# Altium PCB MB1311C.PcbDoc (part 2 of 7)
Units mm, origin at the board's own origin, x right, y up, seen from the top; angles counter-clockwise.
Board outline 100.03 x 67.03 mm, 6 copper layers (Top Layer, layer2, layer3, layer4, layer5, Bottom Layer), stack 1.208 mm thick; 366 components, 356 nets, 1582 pads, 964 vias.
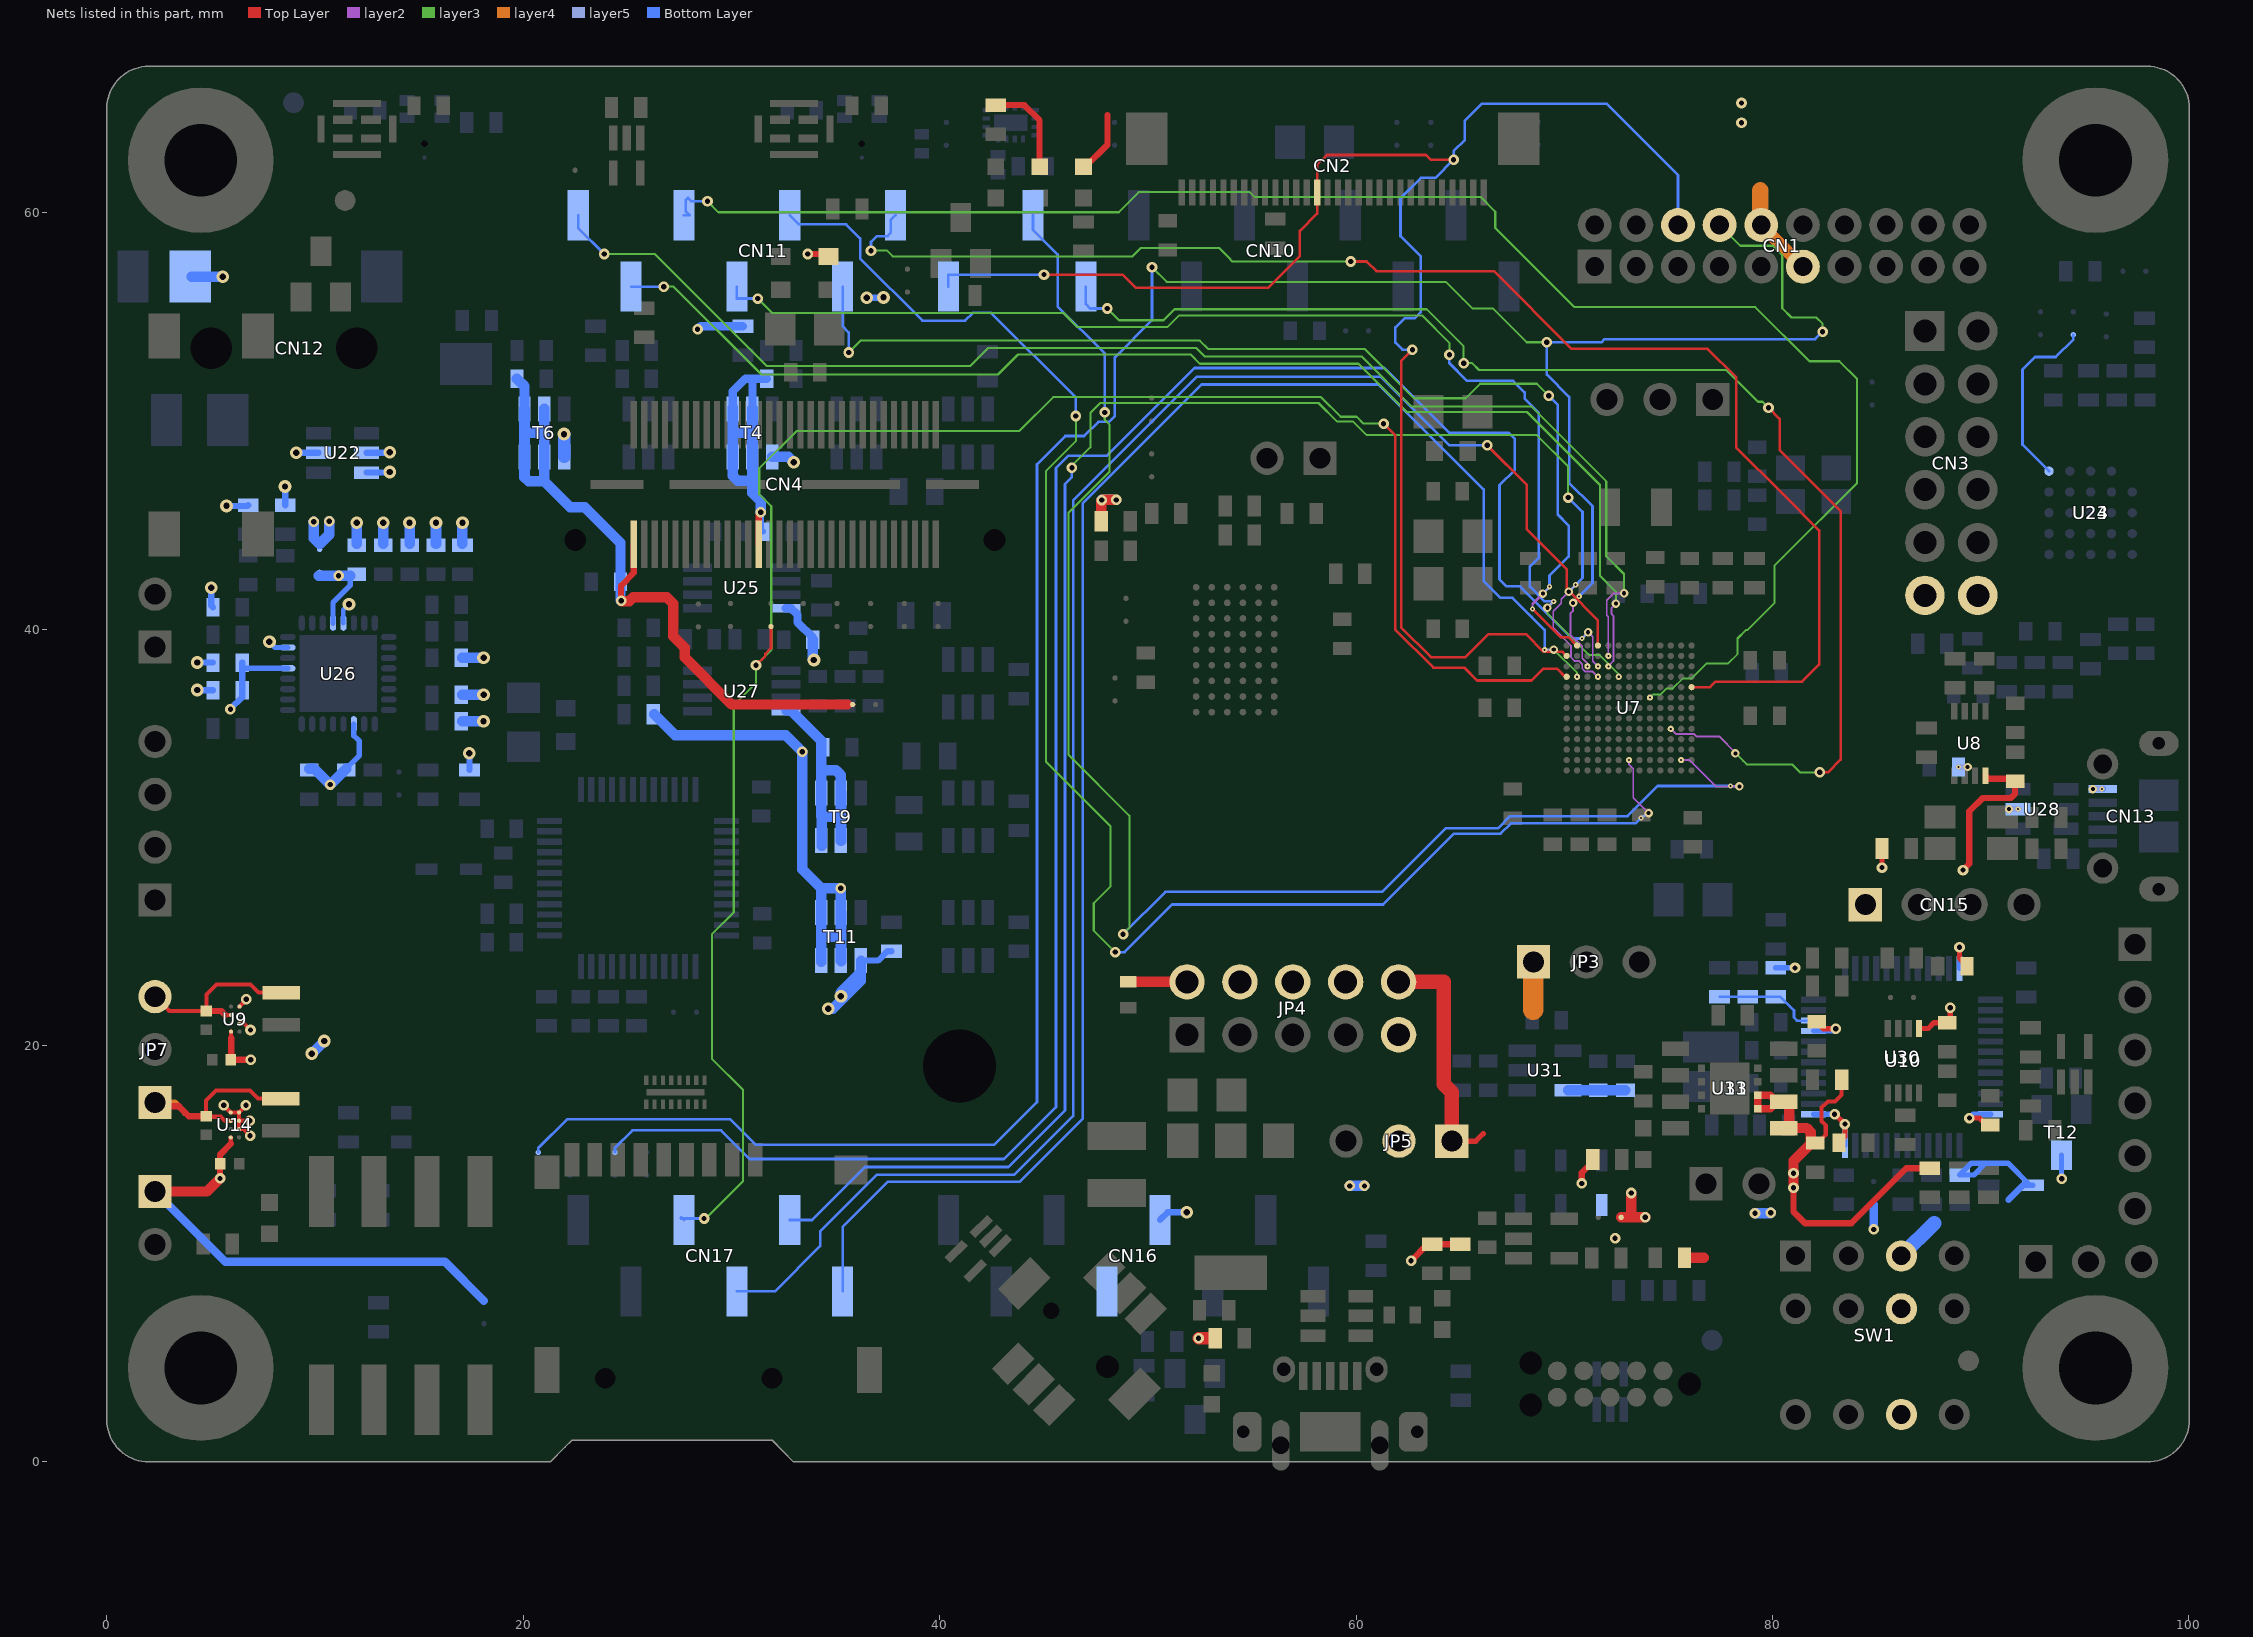
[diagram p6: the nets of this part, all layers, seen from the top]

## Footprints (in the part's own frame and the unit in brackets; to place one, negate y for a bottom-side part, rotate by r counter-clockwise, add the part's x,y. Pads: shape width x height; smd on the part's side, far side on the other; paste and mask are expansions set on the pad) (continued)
ICC_MINI-BGA48_6X8_P075 [mm]
  round 0.32 smd mask+0.05: A1(-1.875,2.625) A2(-1.125,2.625) A3(-0.375,2.625) A4(0.375,2.625) A5(1.125,2.625) A6(1.875,2.625) B1(-1.875,1.875) B2(-1.125,1.875) B3(-0.375,1.875) B4(0.375,1.875) B5(1.125,1.875) B6(1.875,1.875) C1(-1.875,1.125) C2(-1.125,1.125) C3(-0.375,1.125) C4(0.375,1.125) C5(1.125,1.125) C6(1.875,1.125) D1(-1.875,0.375) D2(-1.125,0.375) D3(-0.375,0.375) D4(0.375,0.375) D5(1.125,0.375) D6(1.875,0.375) E1(-1.875,-0.375) E2(-1.125,-0.375) E3(-0.375,-0.375) E4(0.375,-0.375) E5(1.125,-0.375) E6(1.875,-0.375) F1(-1.875,-1.125) F2(-1.125,-1.125) F3(-0.375,-1.125) F4(0.375,-1.125) F5(1.125,-1.125) F6(1.875,-1.125) G1(-1.875,-1.875) G2(-1.125,-1.875) G3(-0.375,-1.875) G4(0.375,-1.875) G5(1.125,-1.875) G6(1.875,-1.875) H1(-1.875,-2.625) H2(-1.125,-2.625) H3(-0.375,-2.625) H4(0.375,-2.625) H5(1.125,-2.625) H6(1.875,-2.625)
  silkscreen extent -3.17,-4.05 3.05,4.18, body extent -3.05,-4.05 3.06,4.06, height 1.2
ICC_MINISO8_3X3_P065 [mm]
  rect 0.4x1.4 smd mask+0.05: 1(0.975,2.125) 2(0.325,2.125) 3(-0.325,2.125) 4(-0.975,2.125) 5(-0.975,-2.125) 6(-0.325,-2.125) 7(0.325,-2.125) 8(0.975,-2.125)
  silkscreen extent -1.6,-1.55 1.6,1.55, body extent -1.6,-2.58 1.6,2.58, height 1.11
ICC_QFN32-EPAD_5X5_P050 [mm]
  oval 0.3x0.75 smd mask+0.05: 1(-1.75,-2.425) 2(-1.25,-2.425) 3(-0.75,-2.425) 4(-0.25,-2.425) 5(0.25,-2.425) 6(0.75,-2.425) 7(1.25,-2.425) 8(1.75,-2.425) 17(1.75,2.425) 18(1.25,2.425) 19(0.75,2.425) 20(0.25,2.425) 21(-0.25,2.425) 22(-0.75,2.425) 23(-1.25,2.425) 24(-1.75,2.425)
  oval 0.75x0.3 smd mask+0.05: 9(2.425,-1.75) 10(2.425,-1.25) 11(2.425,-0.75) 12(2.425,-0.25) 13(2.425,0.25) 14(2.425,0.75) 15(2.425,1.25) 16(2.425,1.75) 25(-2.425,1.75) 26(-2.425,1.25) 27(-2.425,0.75) 28(-2.425,0.25) 29(-2.425,-0.25) 30(-2.425,-0.75) 31(-2.425,-1.25) 32(-2.425,-1.75)
  rect 3.7x3.7 smd mask+0.05: 33(0,0)
  silkscreen extent -2.63,-2.63 2.63,2.63, body extent -2.55,-2.55 2.55,2.55, height 1
ICC_SO8_5X4_P127_DI-DFN8 [mm] "SPT ON MECH-3"
  rect 0.7x1.3 smd paste-10 mask+0.05: 1(-1.905,-2.6) 2(-0.635,-2.6) 3(0.635,-2.6) 4(1.905,-2.6) 5(1.905,2.6) 6(0.635,2.6) 7(-0.635,2.6) 8(-1.905,2.6)
  silkscreen extent -2.58,-2 2.58,2, body extent -2.57,-3 2.57,3, height 1.75
ICC_UFBGA169_7X7_P050 [mm]
  round 0.3 smd mask+0.05: A1(-3,3) A2(-2.5,3) A3(-2,3) A4(-1.5,3) A5(-1,3) A6(-0.5,3) A7(0,3) A8(0.5,3) A9(1,3) A10(1.5,3) A11(2,3) A12(2.5,3) A13(3,3) B1(-3,2.5) B2(-2.5,2.5) B3(-2,2.5) B4(-1.5,2.5) B5(-1,2.5) B6(-0.5,2.5) B7(0,2.5) B8(0.5,2.5) B9(1,2.5) B10(1.5,2.5) B11(2,2.5) B12(2.5,2.5) B13(3,2.5) C1(-3,2) C2(-2.5,2) C3(-2,2) C4(-1.5,2) C5(-1,2) C6(-0.5,2) C7(0,2) C8(0.5,2) C9(1,2) C10(1.5,2) C11(2,2) C12(2.5,2) C13(3,2) D1(-3,1.5) D2(-2.5,1.5) D3(-2,1.5) D4(-1.5,1.5) D5(-1,1.5) D6(-0.5,1.5) D7(0,1.5) D8(0.5,1.5) D9(1,1.5) D10(1.5,1.5) D11(2,1.5) D12(2.5,1.5) D13(3,1.5) E1(-3,1) E2(-2.5,1) E3(-2,1) E4(-1.5,1) E5(-1,1) E6(-0.5,1) E7(0,1) E8(0.5,1) E9(1,1) E10(1.5,1) E11(2,1) E12(2.5,1) E13(3,1) F1(-3,0.5) F2(-2.5,0.5) F3(-2,0.5) F4(-1.5,0.5) F5(-1,0.5) F6(-0.5,0.5) F7(0,0.5) F8(0.5,0.5) F9(1,0.5) F10(1.5,0.5) F11(2,0.5) F12(2.5,0.5) F13(3,0.5) G1(-3,0) G2(-2.5,0) G3(-2,0) G4(-1.5,0) G5(-1,0) G6(-0.5,0) G7(0,0) G8(0.5,0) G9(1,0) G10(1.5,0) G11(2,0) G12(2.5,0) G13(3,0) H1(-3,-0.5) H2(-2.5,-0.5) H3(-2,-0.5) H4(-1.5,-0.5) H5(-1,-0.5) H6(-0.5,-0.5) H7(0,-0.5) H8(0.5,-0.5) H9(1,-0.5) H10(1.5,-0.5) H11(2,-0.5) H12(2.5,-0.5) H13(3,-0.5) J1(-3,-1) J2(-2.5,-1) J3(-2,-1) J4(-1.5,-1) J5(-1,-1) J6(-0.5,-1) J7(0,-1) J8(0.5,-1) J9(1,-1) J10(1.5,-1) J11(2,-1) J12(2.5,-1) J13(3,-1) K1(-3,-1.5) K2(-2.5,-1.5) K3(-2,-1.5) K4(-1.5,-1.5) K5(-1,-1.5) K6(-0.5,-1.5) K7(0,-1.5) K8(0.5,-1.5) K9(1,-1.5) K10(1.5,-1.5) K11(2,-1.5) K12(2.5,-1.5) K13(3,-1.5) L1(-3,-2) L2(-2.5,-2) L3(-2,-2) L4(-1.5,-2) L5(-1,-2) L6(-0.5,-2) L7(0,-2) L8(0.5,-2) L9(1,-2) L10(1.5,-2) L11(2,-2) L12(2.5,-2) L13(3,-2) M1(-3,-2.5) M2(-2.5,-2.5) M3(-2,-2.5) M4(-1.5,-2.5) M5(-1,-2.5) M6(-0.5,-2.5) M7(0,-2.5) M8(0.5,-2.5) M9(1,-2.5) M10(1.5,-2.5) M11(2,-2.5) M12(2.5,-2.5) M13(3,-2.5) N1(-3,-3) N2(-2.5,-3) N3(-2,-3) N4(-1.5,-3) N5(-1,-3) N6(-0.5,-3) N7(0,-3) N8(0.5,-3) N9(1,-3) N10(1.5,-3) N11(2,-3) N12(2.5,-3) N13(3,-3)
  silkscreen extent -3.7,-3.57 3.57,3.7, body extent -3.57,-3.57 3.57,3.57, height 0.61
ICC_UFQFN16-EPAD_2P6X1P8_P040 [mm]
  rect 0.2x0.35 smd mask+0.05: 1(-0.6,-0.775) 2(-0.2,-0.775) 3(0.2,-0.775) 4(0.6,-0.775) 9(0.6,0.775) 10(0.2,0.775) 11(-0.2,0.775) 12(-0.6,0.775)
  rect 0.35x0.2 smd mask+0.05: 5(1.175,-0.6) 6(1.175,-0.2) 7(1.175,0.2) 8(1.175,0.6) 13(-1.175,0.6) 14(-1.175,0.2) 15(-1.175,-0.2) 16(-1.175,-0.6)
  rect 1.6x0.8 smd mask+0.05: 17(0,0)
  silkscreen extent -1.33,-0.92 1.33,0.92, body extent -1.33,-0.92 1.33,0.92, height 0.56
ICC_VFBGA54_6X8_P075 [mm]
  round 0.32 smd mask+0.05: A1(-1.875,3) A2(-1.125,3) A3(-0.375,3) A4(0.375,3) A5(1.125,3) A6(1.875,3) B1(-1.875,2.25) B2(-1.125,2.25) B3(-0.375,2.25) B4(0.375,2.25) B5(1.125,2.25) B6(1.875,2.25) C1(-1.875,1.5) C2(-1.125,1.5) C3(-0.375,1.5) C4(0.375,1.5) C5(1.125,1.5) C6(1.875,1.5) D1(-1.875,0.75) D2(-1.125,0.75) D3(-0.375,0.75) D4(0.375,0.75) D5(1.125,0.75) D6(1.875,0.75) E1(-1.875,0) E2(-1.125,0) E3(-0.375,0) E4(0.375,0) E5(1.125,0) E6(1.875,0) F1(-1.875,-0.75) F2(-1.125,-0.75) F3(-0.375,-0.75) F4(0.375,-0.75) F5(1.125,-0.75) F6(1.875,-0.75) G1(-1.875,-1.5) G2(-1.125,-1.5) G3(-0.375,-1.5) G4(0.375,-1.5) G5(1.125,-1.5) G6(1.875,-1.5) H1(-1.875,-2.25) H2(-1.125,-2.25) H3(-0.375,-2.25) H4(0.375,-2.25) H5(1.125,-2.25) H6(1.875,-2.25) J1(-1.875,-3) J2(-1.125,-3) J3(-0.375,-3) J4(0.375,-3) J5(1.125,-3) J6(1.875,-3)
  silkscreen extent -3.17,-4.05 3.05,4.18, body extent -3.05,-4.05 3.05,4.05, height 1.01
ICC_VSSOP8_DCU_R-PDSO-G8_2X2P30_P050 [mm]
  rect 0.3x0.8 smd mask+0.05: 1(-0.75,-1.55) 2(-0.25,-1.55) 3(0.25,-1.55) 4(0.75,-1.55) 5(0.75,1.55) 6(0.25,1.55) 7(-0.25,1.55) 8(-0.75,1.55)
  silkscreen extent -1.05,-1.2 1.05,1.2, body extent -1.05,-1.62 1.05,1.62, height 0.9
IND_MURATA_DFE201610C [mm]
  rect 0.65x1.8 smd mask+0.05: 1(-0.775,0) 2(0.775,0)
  silkscreen extent -0.33,-0.9 0.33,0.9, body extent -1.1,-0.9 1.1,0.9, height 1
L0603 [mm]
  rect 0.8x0.95 smd mask+0.05: 1(-0.8,0) 2(0.8,0)
  silkscreen extent -1.33,-0.6 1.33,0.6, body extent -0.87,-0.47 0.87,0.47, height 0.95
LED_0603_GREEN_H0P8 [mm]
  rect 0.8x0.8 smd mask+0.05: 1(-0.75,0) 2(0.75,0)
  silkscreen extent -0.25,-0.4 1.25,0.4, body extent -0.8,-0.4 0.8,0.4, height 0.8
LED_0603_ORANGE_H0P4 [mm]
  rect 0.8x0.8 smd mask+0.05: 1(-0.75,0) 2(0.75,0)
  silkscreen extent -0.25,-0.4 1.25,0.4, body extent -0.8,-0.4 0.79,0.4, height 0.4
LED_0603_RED_H0P4 [mm]
  rect 0.8x0.8 smd mask+0.05: 1(-0.75,0) 2(0.75,0)
  silkscreen extent -0.25,-0.4 1.25,0.4, body extent -0.8,-0.4 0.79,0.4, height 0.4
LED_BI-GR_HSMF-A201-A00J1 [mm]
  rect 1.1x1.5 smd mask+0.05: 1(-0.75,-1.5) 2(-0.75,1.5) 3(0.75,1.5) 4(0.75,-1.5)
  silkscreen extent -1.65,-1.85 1.65,1.85, body extent -1.5,-1.85 1.5,1.85, height 2.1
MIC_HCLGA_3X4X1_4LD [mm]
  rect 0.4x0.95 smd paste+0 mask+0.05: 1(0.45,-0.675) 2(0.45,0.675) 3(-0.45,0.675) 4(-0.45,-0.675)
  rect 1.3x0.35 smd paste+0 mask+0.05: 5(0,-1.725) 6(0,1.725)
  rect 0.35x2.3 smd paste+0 mask+0.05: 7(1.225,0) 8(-1.225,0)
  silkscreen extent -1.55,-2.05 1.55,2.05, body extent -1.45,-1.95 1.45,1.95, height 1
MIC_STM_MP23DB01MMTR#1 [mm]
  rect 0.725x0.522 smd mask+0.05: 1(-0.838,1.364) 2(-0.838,0.542) 4(0.838,0.542) 5(0.838,1.364)
  round 0.2 smd mask+0.05: 3(0,-1.373)
  round 0 hole 0.325 unplated mask+0.05: 6(0,-0.71)
  Top Layer drawing of 16384 lines, arcs and shapes, not listed
  silkscreen extent -1.33,-1.75 1.33,1.75, body extent -1.33,-1.76 1.33,1.75, height 1.09
MIC_STM_MP23DB01MMTR#2 [mm]
  rect 0.725x0.522 smd mask+0.05: 1(-0.838,1.364) 2(-0.838,0.542) 4(0.838,0.542) 5(0.838,1.364)
  round 0.2 smd mask+0.05: 3(0,-1.373)
  round 0 hole 0.325 unplated mask+0.05: 6(0,-0.71)
  Top Layer circle w0.3: c0,-0.71 r0.663
  silkscreen extent -1.33,-1.75 1.33,1.75, body extent -1.33,-1.76 1.33,1.75, height 1.09
MOS_SOT23 [mm]
  rect 1x1.4 smd mask+0.05: 1(-0.95,-1.1) 2(0.95,-1.1) 3(0,1.1)
  silkscreen extent -1.63,-0.82 1.63,0.82, body extent -1.56,-1.25 1.56,1.25, height 1.1
MOS_SOT23-5L [mm]
  rect 0.6x1.3 smd mask+0.05: 1(-0.95,-1.1) 2(0,-1.1) 3(0.95,-1.1) 4(0.95,1.1) 5(-0.95,1.1)
  silkscreen extent -1.6,-0.95 1.6,0.97, body extent -1.52,-1.25 1.52,1.25, height 1.45
MOS_SOT23-6L [mm]
  rect 0.6x1.2 smd mask+0.05: 1(-0.95,-1.15) 2(0,-1.15) 3(0.95,-1.15) 4(0.95,1.15) 5(0,1.15) 6(-0.95,1.15)
  silkscreen extent -1.53,-0.87 1.53,0.87, body extent -1.52,-1.5 1.52,1.5, height 1.3
NPN_SOT23 [mm]
  rect 1x1.4 smd mask+0.05: 1(-0.95,-1.1) 2(0.95,-1.1) 3(0,1.1)
  silkscreen extent -1.63,-0.82 1.63,0.82, body extent -1.56,-1.25 1.56,1.25, height 1.1
PTH_350_700 [mm]
  round 7 hole 3.5 mask+0.05: 1(0,0)
  silkscreen extent -3.75,-3.75 3.75,3.75
R0402 [mm]
  rect 0.51x0.7 smd mask+0.05: 1(-0.45,0) 2(0.45,0)
  silkscreen extent -0.72,-0.43 0.72,0.43, body extent -0.52,-0.3 0.52,0.3, height 0.4
R0603 [mm]
  rect 0.64x1 smd mask+0.05: 1(-0.7,0) 2(0.7,0)
  silkscreen extent -1.05,-0.58 1.05,0.58, body extent -0.9,-0.5 0.9,0.5, height 0.56
R0805 [mm]
  rect 0.85x1.3 smd mask+0.05: 1(-0.875,0) 2(0.875,0)
  silkscreen extent -0.33,-0.67 0.33,0.67, body extent -1.05,-0.68 1.05,0.68, height 0.65
REG_SOT223-TAB [mm]
  rect 1.5x1.65 smd mask+0.05: 1(-2.3,-3.175) 2(0,-3.175) 3(2.3,-3.175)
  rect 3.5x1.65 smd mask+0.05: 4(0,3.175)
  silkscreen extent -3.35,-2.15 3.35,2.12, body extent -3.35,-3.48 3.35,3.48, height 1.8
SOLDER-BRIDGE_R0603-0R [mil]
  round 10 smd paste-393.7: 1(-19.69,0) 2(23.62,0)
  Top Layer region: -5.91,19.68 13.78,0 -5.91,-19.68 47.24,-19.68 47.24,19.68 -5.91,19.68
  Top Layer region: -47.24,-19.68 -47.24,19.68 -15.75,19.68 3.94,0 -15.75,-19.68 -47.24,-19.68
  silkscreen extent -50,-23 50,23, body extent -36,-20 36,20, height 22
SWI_GRAYHILL-INC_EDG-501S_DI [mm] "ATTENTION DOUBLE IMPLANTATION AVEC SWITCH RA PROJET MB1311_RevA"
  rect 1.5x1.5 hole 0.9 mask+0.05: 1(-3.81,-3.81)
  round 1.5 hole 0.9 mask+0.05: 2(-1.27,-3.81) 3(1.27,-3.81) 4(3.81,-3.81) 5(3.81,-1.27) 5(3.81,3.81) 6(1.27,-1.27) 6(1.27,3.81) 7(-1.27,-1.27) 7(-1.27,3.81) 8(-3.81,-1.27) 8(-3.81,3.81)
  Top Layer region: 3.15,-1.32 4.47,-1.32 4.47,3.86 3.15,3.86 3.15,-1.32
  Top Layer region: -4.47,-1.32 -3.15,-1.32 -3.15,3.86 -4.47,3.86 -4.47,-1.32
  Top Layer region: -1.93,-1.32 -0.61,-1.32 -0.61,3.86 -1.93,3.86 -1.93,-1.32
  Top Layer region: 0.61,-1.32 1.93,-1.32 1.93,3.86 0.61,3.86 0.61,-1.32
  silkscreen extent -5.85,-5 5.85,5, body extent -5.85,-5 5.85,5, height 6.9
SWI_WEALTHMETAL_TD-0341_4P [mm]
  rect 1.52x2.16 smd mask+0.05: 1(-2.25,-4.75) 2(-2.25,4.75) 3(2.25,-4.75) 4(2.25,4.75)
  silkscreen extent -3,-3.5 3,3.5, body extent -3,-5.15 3,5.15, height 7.55
SWI_XIEJIA_MT-008A_6P [mm]
  rect 1.8x1.1 smd mask+0.05: 1(-3.1,1.4) 2(-3.1,0) 3(-3.1,-1.4) 4(3.1,1.4) 5(3.1,0) 6(3.1,-1.4)
  rect 2.2x1.4 smd mask+0.05: 7(0,3.75) 8(0,-3.75)
  round 0 hole 0.8 unplated mask+0.05: NPTH1(0,1.9)
  round 0 hole 1.1 unplated mask+0.05: NPTH2(0,-1.9)
  silkscreen extent -3.7,-3.7 3.7,3.7, body extent -3.85,-3.75 3.85,3.75, height 5.2

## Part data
B1: library part "SW PUSHBUTTON", "SE Push Button TD-0341 [RESET/Black]"
B2: library part MT-008A, "Joystick"
C1 C2 C3 C5 C7 C10 C12 C14 C15 C16 C17 C18 C19 C20 C21 C22 C23 C24 C26 C27 C28 C29 C31 C32 C34 C35 C37 C40 C44 C45 C48 C49 C52 C53 C57 C60 C61 C64 C65 C66 C69 C70 C72 C73 C74 C78 C79 C80 C81 C83 C84 C85 C88 C89 C90 C92 C94 C97: library part Cap, "Capacitor,100nF,10%,16V,X7R,0603,YAGEO"
C4 C36 C46: library part "Cap Pol1", "TAN Capacitor,10uF,10%,16V,A Type,AVX"
C6: library part "Cap Pol1", "TAN Capacitor,4.7uF,10%,16V,A Type,AVX"
C8 C13 C75 C87: library part "Cap Pol1", "Tan Capacitor,1uF,10%,16V,Tan-A,TAJA105K016R"
C9 C11: library part Cap, "Capacitor,5.6pF,0.25P,50V,NPO,0603"
C25: library part Cap_2.2uF_X5R_10%_0603, "Capacitor,2.2uF,16V,X5R,10%,0603,YAGEO"
C30 C38: library part Cap, "Capacitor,10uF,0402,GRM155R60J106ME11"
C33 C42: library part Cap, "Capacitor,0402,4.7uF"
C39: library part "Cap Pol1", "Tan Capacitor,10uF,10%,25V,Tan-B,TAJB106K025RNJ"
C41 C55 C56 C62 C63 C67 C68 C71 C82 C95 C96: library part Cap, "Capacitor,1uF,0603,16V,10%,X5R,YAGEO"
C43: library part Cap, "Capacitor,4.7uF,16V, X5R,10%,0603"
C47: library part Cap_1uF_X5R_10%_0603, "Capacitor,1uF,16V,X5R,10%,0603,YAGEO"
C50 C51: library part Cap, "Capacitor,6.8pF,0.25P,50V,NPO,0603"
C54: library part Cap, "Capacitor,10uF,10%,10V,X5R,0603,C1608X5R1A106KT000E"
C58 C59: library part Cap, "Capacitor,22nF,10%,25V,X7R,0603"
C76 C77: library part Cap, "Capacitor,150pF,0603,50V,5%,NPO"
C86 C91: library part Cap, "Capacitor,10nF,0603,50V,10%,X7R,YAGEO;"
C93 C98: library part Cap, "Capacitor,10pF,5%,50V,NPO,0603,YAGEO"
C99 C100 C101: library part Cap, "Capacitor,100nF,10%,16V,X7R,0603,YAGEO", Manuf_1=YAGEO, Manuf_Part_1=CC0603KRX7R7BB104
CN1: library part "Header 10X2A", "Header, 10-Pin, Dual row"
CN2: library part FPU330ZH-BT1D3-CA, "TOWNES -  Connector FFC/FPC ZIF 0.5mm 30 pins, Lower Contacts"
CN3: library part "Header 6X2A", "Header, 6-Pin, Dual row"
CN4: library part QSH-030-01-F-D-A, "HIGH SPEED SOCKET STRIP, .5mm PITCH, 60 PINS"
CN5: library part "Header 6", "Header, 6-Pin"
CN6: library part MR01A-01211, "micro-SD card connector top mount push-push", Manuf_1=ATOM
CN7: library part SSM-104-L-DH, "Header, 5-Pin, Dual row"
CN8: library part Tag-10_C, "Footprint for TC2050-IDC-430 plug of nails (TM) cable for MP430"
CN9: library part 475900001
CN10: library part "Header 10X1_Female", "Header, 10-Pin, Single row,female"
CN11 CN16: library part "Header 8X1_Female", "Header, 8-Pin, Single row,female"
CN12: library part PJ3028B-3
CN13: library part 1050170001
CN14 CN15: library part "Header 4", "Header, 4-Pin"
CN17: library part "Header 6X1_Female", "Header, 6-Pin, Single row,female"
D1 D2: library part ESDA7P60-1U1M, "High power transient voltage suppressor, 7V breakdown"
D3 D4 D5 D6 D7: library part BAT60JFILM, "BAT60JFILM"
H1 H2 H3 H4: library part "POSITION HOLE"
JP1: library part Jumper3, "Jumper 3 pins"
JP2 JP8 JP9: library part JP2
JP3 JP5 JP7 JP10: library part Jumper3
JP4: library part "Header 5X2M", "Pin Header male,2.54mm,2*5,L=11.6,180,1U,DIP"
JP6: library part JP2, "2 PIN Jumper"
L1 L2 L3: library part Inductor, "100uH Bead"
L4 L5: library part Inductor, "Inductor"
L6: library part BEAD_600R_350MA_0603, "Bead,600R,350mA,0603,FCM1608KF-601T03,Tai-tech"
LD1: library part LED2, "LED,Orange,0603"
LD2 LD3 LD6 LD8: library part LED2, "LED,Green,0603"
LD4: library part LD_BICOLOR_CMS, "Bicolor Led"
LD5 LD7: library part LED2, "LED, Red ,0603"
R1 R7 R8 R9 R10 R29 R34 R44 R47 R48 R80 R83 R96 R101: library part res1, "Resistor,10K,0603,1%,YAGEO"
R2: library part res1, "Resistor, 510R , 0603,1%,YAGEO"
R3: library part res1, "Resistor,680R,0603,1%,YAGEO"
R4: library part res1, "Resistor, 22 ,0603,1%,YAGEO"
R5 R95: library part res1, "Resistor,510R,0603,1%,YAGEO"
R6: library part res1, "Resistor, 1M , 0603"
R11 R13 R14 R17 R20 R22 R24 R31 R41 R61 R79 R82 R88 R97: library part res1, "Resistor, 0 ,0603,1%,YAGEO"
R12: library part res1, "Resistor,10K,0603,1%,YAGEO", Manuf_1=YAGEO, Manuf_Part_1=RC0603FR-07100KL
R15 R16 R18 R19 R25 R49 R50 R59 R74 R84 R86 R87 R89 R90 R91 R102 R106: library part res1, "Resistor,100K,0603,1%,YAGEO"
R21 R23 R26 R28 R30 R32 R35 R42 R75 R94 R110 R111 R115: library part res1, "Resistor, 100 ,0603,1%,YAGEO"
R27 R64: library part res1, "Resistor,2.2K,0603,1%,YAGEO"
R33 R37: library part res1, "Resistor"
R36: library part res1, "Resistor,36K,0603,1%,YAGEO"
R38: library part res1, "Resistor, 620R , 0603,1%,YAGEO"
R39 R40 R113: library part res1, "Resistor, 47K,0603,1%,YAGEO"
R43: library part res1, "Resistor, 330R , 0603,1%,YAGEO"
R45 R46: library part Res_10K_1%_0402, "Resistor,10K,0402,1%,YAGEO"
R51 R52 R53 R63 R67 R68 R69 R71 R72 R73 R78: library part res1, "Resistor, 33 ,0603,1%,YAGEO"
R54 R56 R107 R108 R112: library part Res1, "Resistor"
R55: library part Res_1_1%_0805, "Resistor,1,0805,1%,YAGEO"
R57 R58: library part res1, "Resistor,50R,0603,1%,YAGEO"
R60 R65: library part res1, "Resistor,6.04K,0603,1%,YAGEO"
R62: library part Res_10K_1%_0805, "Resistor,10K,0805,1%,YAGEO"
R66 R76: library part res1, "Resistor,300K,0603,1%,YAGEO"
R70: library part res1, "Resistor,11K,0603,1%,YAGEO"
R77: library part res1, "Resistor,357K,0603,1%,YAGEO"
R81: library part Res_24_1%_0805, "Resistor,24,0805,1%,YAGEO"
R85: library part Res_620_1%_0805, "Resistor,620,0805,1%,YAGEO"
R92 R93 R105: library part res1, "Resistor,4.7K,0603,1%,YAGEO"
R98 R99 R100: library part res1, "Resistor,1.5K,0603,1%,YAGEO"
R103: library part Res_0_5%_0402, "Resistor,0,0603,5%,YAGEO"
R104: library part res1, "Resistor,2.7K,0603,1%,YAGEO"
R109: library part res1, "Resistor,1K,0603,1%"
R114: library part res1, "Resistor, 10K,0603,1%,YAGEO"
R116: library part res1, "Resistor,56K,0603,1%,YAGEO", Manuf_1=YAGEO, Manuf_Part_1=RC0603FR-0756KL
R117: library part res1, "Resistor,6.8K,0603,1%,YAGEO", Manuf_1=YAGEO, Manuf_Part_1=RC0603FR-076K8L
R118 R119 R120: library part res1, "Resistor, 0 ,0603,1%,YAGEO", Manuf_1=YAGEO, Manuf_Part_1=RC0603JR-070RL
SB1 SB2 SB3 SB5 SB6 SB8 SB9 SB10 SB11 SB12 SB14 SB15 SB22 SB23 SB24 SB26 SB29 SB30 SB31 SB33 SB35 SB37: library part SB_ON, "Solder Bridge ON"
SB4 SB7 SB13 SB16 SB17 SB18 SB19 SB20 SB21 SB25 SB27 SB28 SB32 SB34 SB36 SB39: library part SB_OFF, "Solder Bridge OFF"
SB38: library part SB_ON, "Solder Bridge ON", Manuf_1=YAGEO, Manuf_Part_1=RC0603JR-070RL
SW1: library part EDG-501S, "Gold Plated Contacts,4PST,1x4 Switch"
T1: library part 2N7000
T2 T3 T4 T5 T6 T7 T8 T9 T10 T11: library part STT7P2UH7, "STripFET VII DeepGATE Power MOSFET, P-CHANNEL 20 V, 0.0146, 7 A - SOT23-6L"
T12 T13: library part NPN, "NPN Bipolar Transistor"
U1 U2: library part MP34DT01TR, "MEMS audio sensor"
U3 U12 U17: library part ESDALC6V1W5, "Quad Transil array for ESD protection"
U4: library part ESDA6V1L, "Dual Transil array ESD protection"
U5: library part IS66WV1M16EBLL-55BLI, "16M bit static RAMs organized as 1024K words by 16 bits"
U6: library part IS66WVC2M16ECLL-7010BLI, "32Mb Burst PSRAM , 104 MHz, 3V, organized as 2M words by 16 bits"
U7: library part STM32L4R9AII6U
U8 U10: library part SN74LVC2T45DCUT
U9 U14: library part TPS62743, "High Efficiency Buck Converter"
U11: library part ST890CDR
U13: library part EMIF06-MSD02N16, "6-line IPAD, EMI filter and ESD for SDcard2.0"
U15: library part LD1117S18TR, "Adjustable and fixed low drop positive voltage regulator"
U16: library part STMPS2141STR, "Enhanced single channel power switches"
U18: library part USBLC6-4SC6, "USB ESD protection"
U19 U20: library part MP23DB01MM, "MEMS micro"
U21: library part STG3692QTR, "Low voltage high bandwidth quad SPDT switch"
U22: library part ESDA6V1BC6, "Quad Bidir supressor ESD protection"
U23: library part MT35XL512ABA1G12-0SIT, "512Mb, 3V, Octal I/O XTRM Flash Memory, 133 MHz, DDR"
U24: library part MX25LM51245GXDI00, "512Mb, 3V, CMOS, MXSMIO Octal I/O FLASH MEMORY, 133 MHz, DTR"
U25 U27: library part TSZ122IST, "Very high accuracy (5 ?) zero drift 5 V dual OpAmp"
U26: library part CS42L51-CNZ, "Low-Power, Stereo Codec with Headphone Amp"
U28: library part USBLC6-2SC6
U29: library part MFX, "Multifunction expander"
U30: library part STM32F10x(48pin), "IC,STM32F103CBT6,LQFP-48"
U31: library part LD3985M33R, "Ultra low drop-low noise BiCMOS voltage, regulators low ESR capacitors compatible"
U32: library part ESDALC6V1W5, "Quad Transil array for ESD protection", Manuf_1=STM
U33: library part ST890DTR, Manuf_1=ST
X1: library part CRYSTAL_32K, "32.768kHz Crystal"
X2: library part NX3225GA-16MHz-EXS00A-CG04815
X3: library part XTAL_8M_NX3225GD, "Crystal 8Mhz, 8pF, -+50PPM, SMD"

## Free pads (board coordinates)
  round 1 smd far side mask+0.5: 2(8.971,65.279) 2(77.095,5.839)
  round 1 smd mask+0.5: 2(11.446,60.584) 2(89.418,4.852)
  round 0.1 hole 3.5 unplated: 3(40.963,19.013)

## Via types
v1: diameter 0.508, hole 0.254, Top Layer to Bottom Layer, tented both sides, 462 vias
v2: diameter 0.61, hole 0.305, Top Layer to Bottom Layer, tented both sides, 126 vias
v3: diameter 0.406, hole 0.203, layer2 to layer5, tented both sides, 109 vias
v4: diameter 0.25, hole 0.1, Top Layer to layer2, tented both sides, 80 vias
v5: diameter 0.25, hole 0.1, Top Layer to layer3, tented both sides, 78 vias
v6: diameter 0.25, hole 0.1, layer5 to Bottom Layer, tented both sides, 52 vias
v7: diameter 0.406, hole 0.203, Top Layer to Bottom Layer, tented both sides, 48 vias
v8: diameter 0.508, hole 0.254, layer2 to layer5, tented both sides, 4 vias
v9: diameter 0.406, hole 0.203, layer2 to layer5, 3 vias
v10: diameter 0.25, hole 0.1, layer5 to Bottom Layer, tented bottom, 1 vias
v11: diameter 0.25, hole 0.1, Top Layer to layer3, tented top, 1 vias

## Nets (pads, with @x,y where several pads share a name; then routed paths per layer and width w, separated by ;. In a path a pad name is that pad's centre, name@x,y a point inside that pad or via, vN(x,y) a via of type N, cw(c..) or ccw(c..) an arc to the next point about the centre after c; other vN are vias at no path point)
1V8_CODEC: C57.1 C71.1 C74.1 C81.1 C82.1 SB29.2 U26.5 U26.12 U26.27 | length 13.6
  Bottom Layer w0.254: C71.1@6.672,38.113 U26.5@8.693,38.113 ; U26.12@10.863,40.283 10.863,41.269 11.688,42.093 C57.1@11.688,42.562 ; C81.1@11.494,33.291 12.129,33.926 12.129,34.615 11.863,34.881 U26.27@11.863,35.443
  Bottom Layer w0.3: v1(5.94,36.152) 5.94,36.162 6.505,36.727 C74.1@6.505,37.057 C71.1@6.505,38.387
  Bottom Layer w0.508: C82.1@9.716,33.291 9.97,33.291 v1(10.732,32.529) C81.1@11.494,33.291 ; 10.181,42.562 C57.1@11.688,42.562
  other v1: 11.134,42.559
1V8_LCD: C60.1 C99.2 CN4.60 SB39.2 T6.1 T6.2 T6.5 T6.6 | length 35.3
  Top Layer w0.3: v1@24.675,41.375 24.703,41.375 24.703,42.089 25.313,42.699 CN4.60@25.313,44.073
  Top Layer w0.5: v1@24.725,41.325 25.1,41.325 25.294,41.519 26.906,41.519 27.2,41.225 27.2,39.662 27.76,39.101 27.76,38.64 30.025,36.375 35.575,36.375
  Bottom Layer w0.5: C99.2@19.7,52.025 20.063,51.662 T6.1@20.063,50.573 ; 20.063,47.292 20.26,47.095 21.013,47.095 22.25,45.858 22.96,45.858 24.673,44.145 C60.1@24.673,42.273 24.673,41.383 v1(24.703,41.353)
  Bottom Layer w0.508: 20.063,47.292 20.063,49.44 ; T6.1@20.063,50.573 20.063,49.44 ; 21.013,47.095 T6.5@21.013,48.273 21.013,49.423 ; T6.2@21.013,50.573 21.013,49.423 ; 20.063,49.44 20.08,49.423 21.013,49.423
3V3_LCD: C52.2 C101.2 CN4.36 T4.1 T4.2 T4.5 T4.6 | length 17.3
  Top Layer w0.3: CN4.36@31.313,44.073 31.313,45.503 v1(31.413,45.603)
  Bottom Layer w0.3: v1(31.413,45.603) 31.413,44.783 C52.2@31.513,44.683
  Bottom Layer w0.4: T4.1@30.063,50.573 30.063,50.623 30.063,51.413 30.675,52.025 30.975,52.025 ; T4.2@31.013,50.573 31.013,51.987 30.975,52.025 ; C101.2@31.7,52.025 30.975,52.025
  Bottom Layer w0.5: 31.013,46.537 31.413,46.137 v1(31.413,45.603)
  Bottom Layer w0.508: T4.1@30.061,50.424 30.061,50.623 30.063,50.623 T4.1@30.063,50.573 30.063,49.44 ; 31.013,46.537 31.013,47.127 ; T4.2@31.013,50.573 31.013,49.423 ; 30.063,49.44 30.063,47.363 30.299,47.127 31.013,47.127 ; 30.063,49.44 30.08,49.423 31.013,49.423 ; 31.013,47.127 T4.5@31.013,48.273 31.013,49.423
5V_STL: D7.1 R103.2 SW1.3 | length 9.2
  Bottom Layer w0.254: 90.263,14.347 91.31,14.347 D7.1@92.374,13.283 ; D7.1@92.033,13.283 D7.1@92.374,13.283 ; D7.1@92.513,13.283 D7.1@92.374,13.283 ; R103.2@88.993,13.773 89.567,14.347 90.247,14.347 89.673,13.773 R103.2@88.993,13.773
  Bottom Layer w0.3: 91.338,12.588 D7.1@92.033,13.283
  Bottom Layer w0.7: SW1.3@86.193,9.893 87.763,11.463
5V_USB_CHARGER: C41.2 C79.1 CN13.1 D4.1 JP4.9 R29.1 R33.2 R34.1 U11.1 U11.2 U28.5 U33.1 U33.2 | length 25.5
  Top Layer w0.2: C41.2@82.063,15.313 82.163,15.313 82.563,15.713 82.563,16.163 82.363,16.363 82.363,17.013 82.663,17.313 83.013,17.313 83.323,17.623 R29.1@83.323,18.353
  Top Layer w0.3: v1(70.843,13.373) 70.843,13.883 71.423,14.463 R33.2@71.363,14.523 ; v1(81.013,13.163) 81.013,12.013 81.563,11.463 83.793,11.463 86.433,14.103 R34.1@87.553,14.103
  Top Layer w0.35: U33.2@79.293,17.532 U33.1@79.293,16.958 79.908,16.958 U11.2@80.225,17.275 ; U33.2@79.293,17.608 79.892,17.608 U11.2@80.225,17.275 ; U11.2@80.275,17.225 U11.2@80.225,17.275
  Top Layer w0.5: U11.1@80.318,16.036 80.318,16.028 80.31,16.036 81.638,16.036 81.85,15.824 C41.2@81.85,15.313 ; U11.1@80.8,16.036 U11.2@80.8,17.175 ; v1(81.013,13.163) v1(81.013,13.863) 81.013,14.463 81.863,15.313 C41.2@82.063,15.313
  layer5 w0.3: v6(88.933,33.373) v3(89.373,33.373) ; v3(91.363,31.353) v6(91.803,31.353) ; v3(95.393,32.313) v10(95.833,32.313)
  Bottom Layer w0.3: CN13.1@95.563,32.313 v10(95.833,32.313) CN13.1@95.863,32.313
  Bottom Layer w0.5: v1(59.693,13.253) v1(60.403,13.253)
  other v1: 72.443,10.743
+1V8: C30.1 JP7.3 L4.2 SB29.1 T6.4 U9.C2 | length 12.3
  Top Layer w0.2: JP7.3@2.313,22.343 3.003,21.653 C30.1@4.783,21.653 4.783,22.443 5.263,22.923 6.903,22.923 7.288,22.538 L4.2@8.373,22.538 ; 5.693,21.463 U9.C2@5.973,21.463
  Top Layer w0.3: C30.1@4.783,21.653 5.503,21.653 5.693,21.463
  Bottom Layer w0.508: v1(9.945,45.153) 9.945,44.365 10.224,44.086 10.679,44.541 v1(10.681,45.178) v1(10.681,45.178)
  Bottom Layer w0.6: T6.4@21.963,48.273 v2(21.963,49.363)
+3V3: C38.1 CN3.6 CN3.12 CN16.4 JP3.1 JP7.1 L5.2 LD1.1 LD2.1 R2.1 R11.2 R38.1 R39.1 R43.1 T4.4 U14.C2 | length 30.2
  Top Layer w0.2: U14.C2@5.953,16.383 5.673,16.383 5.483,16.573 4.763,16.573 4.763,16.603 4.763,17.363 5.243,17.843 6.883,17.843 7.268,17.458 L5.2@8.353,17.458
  Top Layer w0.3: JP7.1@2.313,17.263 2.493,17.083 3.463,17.083 3.943,16.603 4.763,16.603 C38.1@4.783,16.603 ; R2.1@42.693,65.163 44.07,65.163 44.803,64.43 LD1.1@44.803,62.203 ; LD2.1@46.913,62.203 47.003,62.203 48.063,63.263 48.063,64.673 ; v1@47.763,46.173 v1(47.783,46.193) 47.79,46.2 v1@47.798,46.2 ; v1(62.643,9.663) 63.433,10.453 R38.1@63.663,10.453 R39.1@65.003,10.453
  Top Layer w0.5: R11.2@47.763,45.173 v1@47.763,46.173 ; v1@47.798,46.2 v1(48.481,46.2)
  Top Layer w0.6: v1(52.438,5.938) R43.1@53.238,5.938
  layer4 w0.3: JP7.1@2.313,17.263 3.264,17.263 3.759,16.768 ; JP3.1@68.513,24.003 JP3.1@68.523,24.013 JP3.1@69.083,24.013
  layer4 w1: 68.513,21.713 JP3.1@68.513,24.003
  Bottom Layer w0.3: v2(36.5,55.916) 37.292,55.916 v2(37.303,55.927) ; CN16.4@50.582,11.615 50.95,11.983 v2(51.873,11.983)
  Bottom Layer w0.5: T4.4@31.963,48.273 32.733,48.273 v2(32.993,48.013) ; v1(47.783,46.193) 47.79,46.2 v1(48.481,46.2)
  other v1: 78.513,64.313 78.513,65.263
+3V3_ST_LINK: C22.2 C29.1 C31.1 C32.2 C37.1 C40.1 C96.1 C97.1 CN15.1 R22.1 R91.1 SB36.1 T12.3 U8.8 U10.1 U30.1 U30.9 U30.24 U30.36 U30.48 U31.5 | length 28.1
  Top Layer w0.254: C31.1@82.143,21.093 82.433,20.803 v1(83.043,20.803) ; v1(82.983,16.693) 83.013,16.693 v1(83.483,16.223) 83.483,15.613 C40.1@83.193,15.323 ; v1(85.263,28.543) R22.1@85.263,29.463 ; U10.1@87.043,20.813 87.483,20.813 87.763,21.093 C32.2@88.393,21.093 88.543,21.243 v1(88.543,21.813) ; v1(88.983,24.723) 88.983,24.173 C29.1@89.343,23.813 ; v1(89.463,16.513) 89.953,16.513 90.283,16.183 C37.1@90.453,16.183
  Top Layer w0.3: v1(89.153,28.423) 89.453,28.723 89.453,31.243 90.093,31.883 91.443,31.883 91.653,32.093 C22.2@91.653,32.683 91.523,32.813 90.373,32.813 U8.8@90.233,32.953
  layer4 w0.254: CN15.1@84.123,26.763 CN15.1@84.463,26.763
  Bottom Layer w0.254: U31.5@70.183,17.853 U31.5@70.193,17.843 ; R91.1@80.163,23.733 81.073,23.733 v1(81.083,23.723) ; U30.1@81.983,16.693 81.993,16.683 82.003,16.693 v1(82.983,16.693) ; U30.9@81.983,20.693 82.933,20.693 v1(83.043,20.803) ; U30.48@83.483,15.193 v1(83.483,16.223) ; U30.24@88.983,23.693 v1(88.983,24.723) ; v1(89.463,16.513) 89.643,16.693 U30.36@90.483,16.693 ; T12.3@93.883,14.723 93.883,13.603 v1(93.893,13.593)
  Bottom Layer w0.4: v1(84.863,11.163) SB36.1@84.863,12.363
  Bottom Layer w0.5: U31.5@70.193,17.843 C97.1@71.633,17.843 C96.1@72.943,17.843 ; v1(79.163,11.944) 79.894,11.944 v1(79.913,11.963)
+5V: C33.1 C42.1 CN1.6 CN1.15 D1.1 JP4.2 JP4.4 JP4.6 JP4.8 JP4.10 JP5.1 JP9.1 L2.1 R40.1 R50.1 R90.2 SB15.1 SB37.2 SW1.6 T11.4 U9.A2 U9.B1 U9.D1 U14.A2 U14.B1 U14.C1 U14.D1 U14.D2 | length 63.3
  Top Layer w0.2: v1@5.653,17.093 5.623,17.123 v1(5.613,17.123) U14.D2@5.953,16.783 U14.D1@6.353,16.783 ; 5.953,15.273 U14.A2@5.953,15.583 ; 5.973,20.353 U9.A2@5.973,20.663 ; U9.B1@6.373,21.063 6.583,21.063 v1(6.903,20.743) ; U9.D1@6.373,21.863 6.703,22.193 v1(6.703,22.213) ; v1(6.683,17.133) 6.683,17.113 U14.D1@6.353,16.783 ; v1(6.863,16.383) U14.C1@6.353,16.383 ; v1(6.883,15.663) 6.563,15.983 U14.B1@6.353,15.983 U14.C1@6.353,16.383 ; U14.C1@6.353,16.383 U14.D1@6.353,16.783
  Top Layer w0.25: JP5.1@64.603,15.403 65.753,15.403 66.113,15.763
  Top Layer w0.3: v1(5.443,13.613) 5.443,14.763 5.953,15.273 ; C33.1@5.963,19.313 C33.1@5.973,19.313 ; 5.973,20.353 C33.1@5.973,19.313 ; v1(6.913,19.313) C33.1@5.973,19.313 ; v1(33.663,58.013) 34.783,58.013 L2.1@34.663,57.893
  Top Layer w0.5: JP9.1@2.313,12.983 4.813,12.983 v1(5.443,13.613) ; D1.1@49.063,23.068 51.868,23.068 JP4.2@51.883,23.053 ; SB15.1@72.733,11.743 73.296,11.743 ; v1(73.213,12.913) 73.213,11.826 73.296,11.743 ; v1(73.893,11.743) 73.296,11.743 ; R40.1@75.773,9.803 76.703,9.803
  Top Layer w0.7: JP4.10@62.043,23.053 64.213,23.053 64.213,18.14 64.603,17.75 JP5.1@64.603,15.403
  layer4 w0.5: JP4.2@51.883,23.053 JP4.2@52.043,23.053
  layer4 w0.6: CN1.15@79.266,59.587 CN1.6@81.266,57.587
  layer4 w0.8: CN1.15@79.266,59.587 79.413,59.863 79.413,61.063
  Bottom Layer w0.3: T11.4@36.223,24.076 37.046,24.076 37.493,24.523 R90.2@37.693,24.523
  Bottom Layer w0.4: JP9.1@2.313,12.983 5.683,9.613 16.233,9.613 SB37.2@18.113,7.733 ; v1(28.375,54.4) 28.525,54.55 R50.1@30.55,54.55 ; T11.4@36.213,24.076 T11.4@36.223,24.076
  Bottom Layer w0.5: v2(9.842,19.609) 10.444,20.211 v2(10.446,20.211) ; v2(34.652,21.758) 34.871,21.758 36.223,23.11 36.223,23.507 35.26,22.544 v2(35.26,22.359) ; T11.4@36.223,23.563 T11.4@36.223,24.076
A5: SB25.1 U23.A5 U24.A5 | length 8.7
  Bottom Layer w0.127: U23.A5@93.283,47.583 92.013,48.853 92.013,52.463 92.613,53.063 93.603,53.063 94.453,53.913 SB25.1@94.453,54.133
AGND: C54.1 C55.1 C56.1 C57.2 C63.1 C70.1 C71.2 C74.2 C76.2 C77.2 CN12.3 R57.2 R58.2 R59.2 R82.2 U22.2 U22.5 U22.6 U26.7 U26.13 | length 20.3
  Top Layer w0.3: v2(11.633,41.193) v2@11.653,41.173
  Bottom Layer w0.229: U26.13@11.363,40.283 11.363,40.923 v2(11.633,41.193)
  Bottom Layer w0.254: v2(7.811,39.387) 8.085,39.113 U26.7@8.693,39.113
  Bottom Layer w0.3: v2(4.343,37.075) 4.361,37.057 C74.2@5.105,37.057 ; v2(4.343,38.394) 4.35,38.387 C71.2@5.105,38.387 ; v2(5.017,41.978) 5.017,41.124 C63.1@5.105,41.036 ; v2(5.753,45.913) 6.763,45.913 R58.2@6.795,45.945 ; v2(8.563,46.843) 8.573,46.833 R57.2@8.573,45.945 ; v2(9.093,48.473) 9.103,48.463 U22.2@10.173,48.463 ; U22.6@12.473,47.513 13.563,47.513 v2(13.593,47.543) ; U22.5@12.473,48.463 13.563,48.463 v2(13.593,48.493) ; v2(17.413,34.033) 17.423,34.023 R82.2@17.423,33.229
  Bottom Layer w0.508: CN12.3@4.093,56.929 4.087,56.923 v2(5.573,56.923) ; C57.2@12.002,44.086 v2(12.002,45.102) ; C56.1@13.272,44.086 v2(13.272,45.102) ; C55.1@14.542,44.086 v2(14.542,45.102) ; C54.1@15.812,44.086 v2(15.812,45.102) ; C77.2@17.082,35.577 v2(18.095,35.577) ; C76.2@17.082,36.847 v2(18.098,36.847) ; C70.1@17.082,38.625 v2(18.098,38.625) ; R59.2@17.082,44.086 v2(17.082,45.102)
AIN_1: R91.2 R92.1 R93.1 U30.10 | length 5.2
  Bottom Layer w0.127: R93.1@77.463,22.333 R92.1@78.813,22.333 R91.2@80.163,22.333 80.383,22.333 81.033,21.683 81.033,21.343 81.183,21.193 U30.10@81.983,21.193
AMP_5V: C69.2 R79.2 T11.1 T11.2 T11.5 T11.6 U25.8 | length 27.3
  Bottom Layer w0.305: C69.2@33.913,39.493 C69.2@33.913,39.583
  Bottom Layer w0.4: U25.8@32.618,40.996 32.87,40.996 33.173,40.693 33.173,40.323 C69.2@33.913,39.583
  Bottom Layer w0.5: C69.2@33.913,39.493 33.913,38.563 v2(33.963,38.513)
  Bottom Layer w0.508: R79.2@26.302,35.906 27.305,34.903 32.603,34.903 v1(33.403,34.103) 33.403,28.458 34.318,27.543 v1(35.253,27.543) ; T11.1@34.311,26.227 T11.1@34.311,26.426 ; 34.311,27.536 T11.1@34.311,26.426 ; T11.6@34.313,24.026 34.313,25.243 ; T11.2@35.261,26.177 v1@35.261,27.543 ; T11.2@35.263,26.376 35.263,25.226 ; T11.5@35.283,24.056 T11.5@35.263,24.076 35.263,25.226 ; T11.1@34.311,26.426 34.313,26.426 T11.1@34.313,26.376 34.313,25.243 ; 34.313,25.243 34.33,25.226 35.263,25.226
AMP_VDD: C78.1 T9.1 T9.2 T9.5 T9.6 U27.8 | length 12.8
  Bottom Layer w0.4: U27.8@32.618,36.043 U27.8@32.903,36.043
  Bottom Layer w0.508: U27.8@32.903,36.043 34.311,34.635 T9.1@34.311,32.186 ; T9.1@34.311,31.987 T9.1@34.311,32.186 ; 34.313,31.003 T9.1@34.313,32.136 34.313,32.186 T9.1@34.311,32.186 ; 34.317,33.226 35.021,33.226 35.261,32.986 T9.2@35.261,31.937 ; T9.6@34.33,29.59 34.33,30.986 35.263,30.986 ; T9.5@35.263,29.836 35.263,30.986 ; T9.2@35.263,32.136 35.263,30.986
ARD_5V: CN16.5 JP5.2
ARD_A0: CN17.1 U7.M4 | length 81.5
  layer3 w0.088: v3(69.501,39.011) 70.617,37.895 v5(70.617,37.708)
  layer5 w0.127: v6(69.06,39) 69.49,39 v3(69.501,39.011)
  Bottom Layer w0.127: CN17.1@35.342,8.186 35.342,11.282 37.505,13.445 43.845,13.445 46.873,16.473 46.873,46.038 52.582,51.747 61.085,51.747 66.13,46.702 66.13,42.317 66.95,41.497 67.525,41.497 68.438,40.584 69.06,39.962 v6(69.06,39)
ARD_A1: CN17.2 U7.K4 | length 86
  layer2 w0.088: v3(70.218,41.796) 69.854,41.432 69.854,41.228 69.469,40.843 69.469,40.054 70.326,39.197 70.326,38.646 70.514,38.457 70.72,38.457 70.869,38.308 70.869,38.105 71.016,37.959 71.366,37.959 v4(71.617,37.708)
  layer3 w0.102: v1(46.354,47.747) 46.354,47.844 47.241,48.732 47.241,50.373 47.721,50.853 58.196,50.853 59.078,49.971 59.849,49.971 60.507,49.313 68.678,49.313 70.188,47.803 v1(70.188,46.314)
  layer5 w0.127: v3(70.218,41.796) v6(70.549,42.126)
  Bottom Layer w0.127: CN17.2@32.802,11.615 33.875,11.615 36.421,14.161 43.311,14.161 46.023,16.873 46.023,46.963 46.354,47.294 v1(46.354,47.747) ; v1(70.188,46.314) 70.877,45.625 70.877,42.454 v6(70.549,42.126)
ARD_A2: CN17.3 U7.K1 | length 85.1
  Top Layer w0.127: v1(66.303,48.823) 68.203,46.923 68.203,44.784 70.123,42.864 70.123,41.913 71.617,40.419 U7.K1@71.617,39.208
  Bottom Layer w0.127: CN17.3@30.262,8.186 32.086,8.186 34.263,10.363 34.263,11.063 36.993,13.793 43.593,13.793 46.413,16.613 46.413,46.179 52.347,52.113 61.204,52.113 64.494,48.823 v1(66.303,48.823)
ARD_A3: CN17.4 SB7.2 U7.N4 | length 94.1
  Top Layer w0.127: v1(31.183,38.263) 31.628,38.708 31.628,38.807 31.889,39.067 31.903,39.067 SB7.2@31.903,40.123 ; v1(61.324,49.866) 61.879,49.311 61.879,39.984 63.715,38.148 65.198,38.148 65.817,37.529 68.429,37.529 68.988,38.088 69.665,38.088 70.045,37.708 U7.N4@70.117,37.708
  layer3 w0.102: v1(28.688,11.688) 28.763,11.688 30.563,13.488 30.563,17.863 29.063,19.363 29.063,25.338 30.113,26.388 30.113,36.338 31.173,37.398 31.173,38.253 v1(31.183,38.263) 31.913,38.993 31.913,45.903 31.34,46.476 31.34,47.716 33.137,49.513 43.828,49.513 45.452,51.137 58.316,51.137 59.26,50.193 60.03,50.193 60.357,49.866 v1(61.324,49.866)
  Bottom Layer w0.127: CN17.4@27.722,11.615 27.599,11.738 27.574,11.713 27.599,11.688 v1(28.688,11.688)
ARD_A4: SB33.1 U7.K3 | length 93.9
  layer2 w0.088: v3(71.148,39.844) 71.366,39.626 71.366,38.458 v4(71.617,38.208)
  layer5 w0.127: v6(70.849,39.547) v6(70.849,39.547) v3(71.148,39.844)
  Bottom Layer w0.127: SB33.1@24.413,14.863 24.413,15.086 25.25,15.923 29.503,15.923 30.881,14.545 43.095,14.545 45.587,17.037 45.587,47.737 46.18,48.33 48.037,48.33 49.658,49.951 52.243,52.536 61.365,52.536 64.472,49.429 67.319,49.429 67.627,49.12 67.627,47.646 66.892,46.91 66.892,42.384 67.225,42.051 67.875,42.051 70.379,39.547 v6(70.849,39.547)
ARD_A5: CN1.14 SB35.1 U7.L3 | length 129.2
  layer2 w0.088: v3(70.423,41.253) 70.423,40.882 70.298,40.757 70.298,39.734 70.867,39.165 70.867,38.605 71.114,38.358 71.114,38.213 v4(71.119,38.208)
  layer3 w0.102: v1(50.203,57.373) 50.904,56.672 64.313,56.672 65.121,55.864 65.586,55.399 66.567,55.399 68.193,53.773 v1(69.163,53.773) ; CN1.14@77.463,59.407 78.459,58.411 80.013,58.411 80.469,57.955 80.469,55.408 80.914,54.963 82.106,54.963 82.409,54.66 v1(82.409,54.278)
  layer5 w0.127: v3(70.423,41.253) 70.423,41.274 v6(70.719,41.57)
  Bottom Layer w0.127: SB35.1@20.723,14.863 20.723,15.063 22.113,16.453 29.948,16.453 31.169,15.232 42.632,15.232 44.675,17.275 44.675,47.91 46.036,49.271 46.945,49.271 47.621,49.947 48.124,49.947 48.413,50.236 48.413,53.043 50.203,54.833 v1(50.203,57.373) ; v6(70.719,41.57) 71.358,42.209 71.358,45.898 70.235,47.021 70.235,51.153 69.163,52.225 v1(69.163,53.773) 71.782,53.773 71.932,53.923 82.054,53.923 v1(82.409,54.278)
ARD_D0: CN11.1 U7.J2 | length 65.1
  layer2 w0.088: v4(72.117,38.708) 72.117,40.582 72.041,40.657 72.041,41.378 72.376,41.713 v3(72.873,41.713)
  layer3 w0.102: v1(23.893,58.013) 26.313,58.013 31.685,52.641 41.481,52.641 41.783,52.943 42.339,53.499 52.32,53.499 52.733,53.086 60.27,53.086 62.659,50.697 68.414,50.697 72.019,47.092 72.019,45.815 72.019,43.498 72.873,42.644 v3(72.873,41.713)
  Bottom Layer w0.127: CN11.1@22.642,59.875 22.642,59.264 v1(23.893,58.013)
ARD_D1: CN11.2 U7.J3 | length 60.5
  layer2 w0.088: v4(72.117,38.208) 72.117,38.217 72.364,38.464 72.364,40.632 72.276,40.72 72.276,41.016 v3(72.483,41.223)
  layer3 w0.102: v1(26.746,56.446) 27.22,56.446 31.443,52.223 42.803,52.223 43.763,53.183 52.056,53.183 52.499,52.74 60.118,52.74 62.437,50.421 68.215,50.421 71.72,46.916 71.72,42.551 72.483,41.788 v3(72.483,41.223)
  Bottom Layer w0.127: CN11.2@25.182,56.446 v1(26.746,56.446)
ARD_D2: CN11.3 U7.E6 | length 82.9
  layer3 w0.088: v5(74.117,36.708) 74.259,36.85 74.621,36.85 74.919,37.148 75.222,37.148 75.705,37.63 76.118,37.63 76.83,38.342 77.864,38.342 78.321,38.799
  layer3 w0.102: v1(28.853,60.543) 29.376,60.02 48.604,60.02 49.566,60.982 54.89,60.982 55.116,60.756 65.981,60.756 66.688,60.049 66.688,59.264 70.491,55.461 79.18,55.461 81.78,52.861 83.213,52.861 84.066,52.008 84.066,47.013 80.523,43.47 80.095,43.042 80.095,41.244 78.796,39.945 78.724,39.945 78.321,39.542 78.321,38.799
  Bottom Layer w0.127: CN11.3@27.722,59.875 27.995,59.875 27.813,60.057 27.813,60.603 27.917,60.707 28.081,60.543 v1(28.853,60.543)
ARD_D3: CN11.4 U7.H4 | length 58
  layer3 w0.088: v3(69.191,41.026) 69.191,40.756 71.199,38.748 71.706,38.748 72.618,37.836 v5(72.618,37.708)
  layer3 w0.102: v1(31.263,55.873) 31.96,55.176 45.95,55.176 46.624,54.502 50.942,54.502 51.503,55.063 63.167,55.063 64.485,53.745 v1(64.485,53.177)
  layer5 w0.127: v3(69.191,41.026) v6(69.493,41.328)
  Bottom Layer w0.127: CN11.4@30.262,56.446 30.262,55.873 v1(31.263,55.873) ; v1(64.485,53.177) 64.485,52.765 65.327,51.923 67.538,51.923 68.099,51.362 68.099,51.065 68.768,50.396 68.768,43.422 68.351,43.005 68.351,42.035 69.058,41.328 v6(69.493,41.328)
ARD_D4: CN11.5 U7.G12 | length 78.8
  layer2 w0.088: v4(73.117,33.708) 73.117,33.482 73.319,33.28 73.319,31.891 v3(74.051,31.16)
  layer3 w0.102: v1(46.542,50.232) 46.542,49.025 45.115,47.598 45.115,33.613 48.214,30.514 48.214,27.643 47.401,26.83 47.401,25.515 v1(48.433,24.483)
  layer5 w0.127: v6(73.684,30.93) v3(74.051,31.16)
  Bottom Layer w0.127: CN11.5@32.802,59.875 33.237,59.44 35.503,59.44 36.187,58.756 36.187,57.791 39.169,54.809 41.223,54.809 41.602,55.189 42.479,55.189 46.542,51.126 v1(46.542,50.232) ; v1(48.433,24.483) 48.883,24.483 51.171,26.771 61.301,26.771 64.706,30.176 66.947,30.176 67.439,30.668 73.422,30.668 v6(73.684,30.93)
ARD_D5: CN11.6 U7.M1 | length 53
  Top Layer w0.127: v4(68.478,40.963) 69.829,39.612 70.198,39.612 U7.M1@70.602,39.208
  layer2 w0.102: v4(68.478,40.963) 68.478,41.203 v3(68.978,41.703)
  layer3 w0.102: v1(35.633,53.283) 36.2,53.85 52.498,53.85 52.893,53.455 60.406,53.455 62.776,51.085 65.265,51.085 65.959,51.779 68.678,51.779 v1(69.257,51.2)
  layer5 w0.127: v3(68.978,41.703) 69.303,42.028 69.303,42.033 v6(69.296,42.033)
  Bottom Layer w0.127: CN11.6@35.342,56.446 35.342,54.544 35.633,54.253 v1(35.633,53.283) ; v1(69.257,51.2) 69.69,50.767 69.69,45.489 70.212,44.967 70.212,43.476 69.296,42.56 v6(69.296,42.033)
ARD_D6: CN11.7 U7.A5 | length 68.9
  Top Layer w0.127: v1(59.753,57.653) 60.513,57.653 60.978,57.188 66.621,57.188 70.349,53.46 75.749,53.46 76.891,53.46 78.257,52.094 78.257,48.728 80.462,46.523 82.247,44.738 82.247,38.293 81.427,37.473 77.275,37.473 77.01,37.208 U7.A5@76.117,37.208
  layer3 w0.102: v1(36.706,58.174) 37.479,58.174 37.752,57.901 49.265,57.901 49.668,58.304 53.428,58.304 53.963,57.769 53.963,57.744 54.054,57.653 v1(59.753,57.653)
  Bottom Layer w0.127: v1(36.706,58.174) 36.706,58.595 36.983,58.872 37.496,58.872 37.652,59.028 37.652,59.645 CN11.7@37.882,59.875
ARD_D7: CN1.13 CN2.17 CN11.8 U7.N2 | length 82
  Top Layer w0.127: v1(45.013,57.023) 48.794,57.023 49.43,56.387 55.768,56.387 57.303,57.922 57.303,59.123 58.132,59.952 CN2.17@58.132,60.402 ; v1(62.708,53.419) 62.167,52.878 62.167,40.08 63.601,38.646 65.251,38.646 66.356,39.751 68.16,39.751 69.008,38.903 69.922,38.903 U7.N2@70.117,38.708 ; v1(64.686,62.54) 63.586,62.54 63.356,62.77 58.6,62.77 58.132,62.303 CN2.17@58.132,60.973 ; CN2.17@58.132,60.402 CN2.17@58.132,60.973 ; CN2.17@58.132,60.402 CN2.17@58.132,60.973
  Bottom Layer w0.127: CN11.8@40.422,56.447 40.422,57.023 v1(45.013,57.023) ; v1(62.708,53.419) 62.232,53.419 61.891,53.76 61.891,54.48 62.334,54.923 62.801,54.923 63.11,55.232 63.11,57.895 62.136,58.869 62.136,60.69 63.117,61.671 63.817,61.671 v1(64.686,62.54) 64.686,62.951 65.228,63.493 65.228,64.413 66.048,65.233 72.028,65.233 75.463,61.798 CN1.13@75.463,59.813
ARD_D8: CN10.1 U7.B12 | length 74.1
  layer2 w0.088: v4(75.617,33.708) 76.023,33.708 77.288,32.443 v3(78.413,32.443)
  layer3 w0.102: v1(47.934,50.403) 47.934,50.042 48.164,49.812 48.164,47.564 46.193,45.593 46.193,33.955 49.116,31.032 49.116,25.646 v1(48.813,25.343)
  layer5 w0.127: v6(77.993,32.463) v3(78.413,32.443)
  Bottom Layer w0.127: CN10.1@44.486,59.876 44.486,59.173 45.668,57.991 45.668,55.497 47.934,53.231 v1(47.934,50.403) ; v1(48.813,25.343) 50.844,27.374 61.249,27.374 64.305,30.43 66.815,30.43 67.399,31.014 73.038,31.014 74.487,32.463 v6(77.993,32.463)
ARD_D9: CN10.2 U7.C9 | length 64.3
  Top Layer w0.127: v1(79.81,50.63) 80.345,50.095 80.345,48.597 83.28,45.662 83.28,33.725 82.672,33.117 v1(82.266,33.117)
  layer2 w0.088: v4(75.117,35.208) 75.364,34.96 76.221,34.96 76.34,34.841 77.45,34.841 78.22,34.07 v3(78.22,34.025)
  layer3 w0.088: v3(78.22,34.025) 78.244,34.025 78.596,33.673
  layer3 w0.102: v1(48.053,55.393) 48.615,54.831 50.751,54.831 51.281,55.361 63.391,55.361 65.168,53.584 v1(65.168,52.769) 65.577,52.769 65.906,52.44 77.784,52.44 79.31,50.914 79.526,50.914 v1(79.81,50.63) ; 78.596,33.673 78.767,33.502 80.943,33.502 81.327,33.117 v1(82.266,33.117)
  Bottom Layer w0.127: CN10.2@47.026,56.447 47.026,55.601 47.234,55.393 v1(48.053,55.393)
